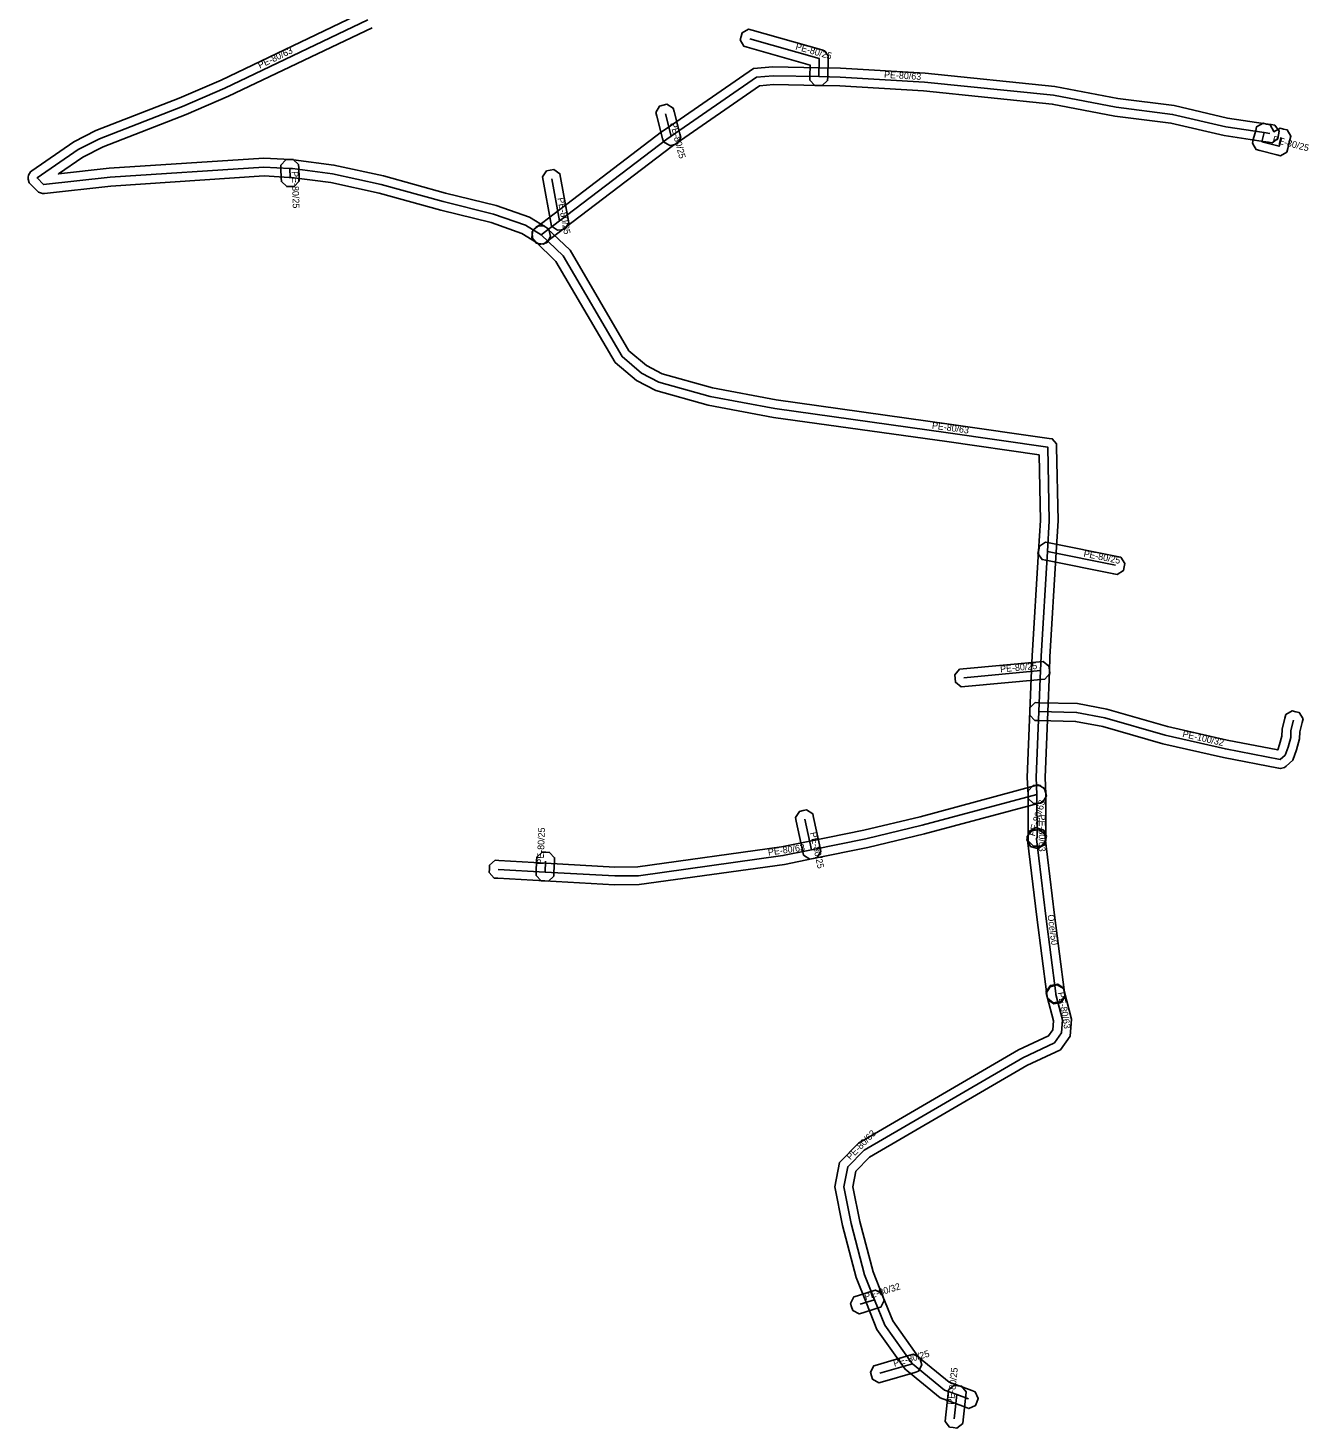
# Model space of a CAD drawing. Extents: x -569373 to -565022, y -1135090 to -1131496.
# Drawn here: x -565683.5 to -565539.4, y -1134292.3 to -1134134.8 of the extents above; entities that cross this region are included whole.
import ezdxf

# ---------------------------------------------------------------- set-up
doc = ezdxf.new("R2010")
doc.units = 0
for name, color, linetype in [('1', 7, 'Continuous'), ('24', 7, 'Continuous'), ('30', 7, 'Continuous')]:
    doc.layers.add(name, color=color, linetype=linetype)

msp = doc.modelspace()

# ---------------------------------------------------------------- linework, layer by layer
at = {"layer": '1'}
msp.add_lwpolyline([(-565644.837, -1134134.732), (-565660.985, -1134142.44), (-565665.759, -1134144.515), (-565675.083, -1134148.145), (-565677.369, -1134149.292), (-565680.107, -1134151.186), (-565674.398, -1134150.554), (-565656.995, -1134149.408), (-565654.019, -1134149.572), (-565653.682, -1134149.594), (-565649.129, -1134150.184), (-565643.55, -1134151.399), (-565636.587, -1134153.333), (-565630.875, -1134154.74), (-565627.127, -1134156.052), (-565625.285, -1134157.189), (-565624.933, -1134157.406), (-565624.742, -1134158.213), (-565624.959, -1134158.565), (-565625.176, -1134158.917), (-565625.983, -1134159.108), (-565626.335, -1134158.891), (-565627.993, -1134157.868), (-565631.445, -1134156.66), (-565637.093, -1134155.267), (-565644.03, -1134153.341), (-565649.471, -1134152.156), (-565653.878, -1134151.586), (-565654.141, -1134151.568), (-565656.985, -1134151.412), (-565674.222, -1134152.546), (-565681.69, -1134153.374), (-565681.92, -1134153.4), (-565682.356, -1134153.243), (-565682.517, -1134153.077), (-565683.237, -1134152.337), (-565683.391, -1134152.179), (-565683.536, -1134151.763), (-565683.515, -1134151.543), (-565683.494, -1134151.324), (-565683.27, -1134150.944), (-565683.089, -1134150.818), (-565678.391, -1134147.568), (-565675.897, -1134146.315), (-565666.521, -1134142.665), (-565661.815, -1134140.62), (-565645.743, -1134132.948)], dxfattribs=at)
for points in [[(-565595.58, -1134140.629), (-565595.57, -1134140.215), (-565595.539, -1134138.951), (-565602.623, -1134136.942), (-565603.021, -1134136.829), (-565603.425, -1134136.105), (-565603.312, -1134135.707), (-565603.199, -1134135.309), (-565602.475, -1134134.905), (-565602.077, -1134135.018), (-565594.247, -1134137.238), (-565593.918, -1134137.331), (-565593.512, -1134137.882), (-565593.52, -1134138.225), (-565593.57, -1134140.265), (-565593.58, -1134140.679), (-565594.181, -1134141.25), (-565594.595, -1134141.24), (-565595.009, -1134141.23)], [(-565626.746, -1134157.496), (-565626.416, -1134157.245), (-565624.356, -1134155.675), (-565612.258, -1134146.461), (-565611.749, -1134146.108), (-565601.928, -1134139.315), (-565599.751, -1134139.139), (-565594.552, -1134139.24), (-565592.132, -1134139.281), (-565582.619, -1134139.853), (-565568.035, -1134141.34), (-565560.953, -1134142.692), (-565554.602, -1134143.494), (-565548.591, -1134144.907), (-565544.313, -1134145.551), (-565543.704, -1134145.641), (-565543.294, -1134145.701), (-565542.801, -1134146.366), (-565542.861, -1134146.776), (-565542.921, -1134147.186), (-565543.586, -1134147.679), (-565543.996, -1134147.619), (-565544.607, -1134147.529), (-565548.969, -1134146.873), (-565554.958, -1134145.466), (-565561.267, -1134144.668), (-565568.325, -1134143.32), (-565582.781, -1134141.847), (-565592.208, -1134141.279), (-565594.588, -1134141.24), (-565599.689, -1134141.141), (-565601.232, -1134141.265), (-565610.611, -1134147.752), (-565611.082, -1134148.079), (-565623.144, -1134157.265), (-565625.204, -1134158.835), (-565625.533, -1134159.086), (-565626.354, -1134158.976), (-565626.605, -1134158.646), (-565626.856, -1134158.317)], [(-565612.044, -1134147.582), (-565612.148, -1134147.181), (-565612.798, -1134144.671), (-565612.902, -1134144.27), (-565612.482, -1134143.556), (-565612.081, -1134143.452), (-565611.68, -1134143.348), (-565610.966, -1134143.768), (-565610.862, -1134144.169), (-565610.212, -1134146.679), (-565610.108, -1134147.08), (-565610.528, -1134147.794), (-565610.929, -1134147.898), (-565611.33, -1134148.002)], [(-565543.388, -1134146.393), (-565543.402, -1134146.447), (-565542.691, -1134146.028), (-565542.29, -1134146.132), (-565541.889, -1134146.235), (-565541.468, -1134146.949), (-565541.572, -1134147.35), (-565541.822, -1134148.32), (-565541.925, -1134148.721), (-565542.639, -1134149.142), (-565543.04, -1134149.038), (-565544.98, -1134148.538), (-565545.382, -1134148.435), (-565545.592, -1134148.076), (-565545.803, -1134147.718), (-565545.697, -1134147.316), (-565545.427, -1134146.286), (-565545.322, -1134145.885), (-565544.607, -1134145.468), (-565544.206, -1134145.573), (-565543.805, -1134145.678)], [(-565653.092, -1134150.127), (-565653.08, -1134150.541), (-565653.05, -1134151.571), (-565653.038, -1134151.985), (-565653.607, -1134152.588), (-565654.021, -1134152.6), (-565654.435, -1134152.612), (-565655.038, -1134152.043), (-565655.05, -1134151.629), (-565655.08, -1134150.599), (-565655.092, -1134150.185), (-565654.523, -1134149.582), (-565654.109, -1134149.57), (-565653.695, -1134149.558)], [(-565624.66, -1134157.057), (-565624.734, -1134156.649), (-565625.594, -1134151.929), (-565625.668, -1134151.521), (-565625.197, -1134150.84), (-565624.789, -1134150.766), (-565624.381, -1134150.692), (-565623.7, -1134151.163), (-565623.626, -1134151.571), (-565622.766, -1134156.291), (-565622.692, -1134156.699), (-565623.163, -1134157.38), (-565623.571, -1134157.454), (-565623.979, -1134157.528)], [(-565625.417, -1134157.031), (-565625.118, -1134157.318), (-565622.557, -1134159.775), (-565615.933, -1134171.078), (-565613.969, -1134172.744), (-565612.192, -1134173.664), (-565606.552, -1134175.235), (-565599.357, -1134176.603), (-565579.9, -1134179.32), (-565568.678, -1134180.93), (-565568.315, -1134180.982), (-565567.828, -1134181.532), (-565567.82, -1134181.899), (-565567.649, -1134190.21), (-565567.862, -1134193.73), (-565568.571, -1134205.492), (-565568.641, -1134207.102), (-565568.831, -1134211.711), (-565569.129, -1134219.067), (-565569.041, -1134220.943), (-565569.022, -1134221.357), (-565569.579, -1134221.97), (-565569.993, -1134221.989), (-565570.407, -1134222.008), (-565571.02, -1134221.451), (-565571.039, -1134221.037), (-565571.131, -1134219.073), (-565570.829, -1134211.629), (-565570.639, -1134207.018), (-565570.569, -1134205.388), (-565569.858, -1134193.61), (-565569.651, -1134190.17), (-565569.802, -1134182.789), (-565580.18, -1134181.3), (-565599.683, -1134178.577), (-565607.008, -1134177.185), (-565612.928, -1134175.536), (-565615.091, -1134174.416), (-565617.487, -1134172.382), (-565624.143, -1134161.025), (-565626.502, -1134158.762), (-565626.801, -1134158.475), (-565626.819, -1134157.647), (-565626.532, -1134157.348), (-565626.245, -1134157.049)], [(-565569.07, -1134192.608), (-565568.664, -1134192.689), (-565561.014, -1134194.219), (-565560.608, -1134194.301), (-565560.148, -1134194.99), (-565560.229, -1134195.396), (-565560.311, -1134195.802), (-565561, -1134196.262), (-565561.406, -1134196.181), (-565569.056, -1134194.651), (-565569.462, -1134194.569), (-565569.922, -1134193.88), (-565569.841, -1134193.474), (-565569.759, -1134193.068)], [(-565578.755, -1134206.903), (-565578.343, -1134206.864), (-565569.733, -1134206.064), (-565569.32, -1134206.026), (-565568.683, -1134206.555), (-565568.644, -1134206.967), (-565568.606, -1134207.38), (-565569.135, -1134208.017), (-565569.547, -1134208.056), (-565578.157, -1134208.856), (-565578.57, -1134208.894), (-565579.207, -1134208.365), (-565579.246, -1134207.953), (-565579.284, -1134207.54)], [(-565540.099, -1134212.493), (-565540.2, -1134212.895), (-565540.465, -1134213.943), (-565540.495, -1134214.73), (-565540.825, -1134215.968), (-565541.248, -1134217.146), (-565542.018, -1134217.808), (-565542.192, -1134217.958), (-565542.635, -1134218.076), (-565542.86, -1134218.032), (-565549.036, -1134216.839), (-565555.859, -1134215.289), (-565562.631, -1134213.344), (-565565.685, -1134212.768), (-565569.854, -1134212.67), (-565570.268, -1134212.66), (-565570.84, -1134212.06), (-565570.83, -1134211.646), (-565570.82, -1134211.232), (-565570.22, -1134210.66), (-565569.806, -1134210.67), (-565565.475, -1134210.772), (-565562.169, -1134211.396), (-565555.361, -1134213.351), (-565548.624, -1134214.881), (-565542.955, -1134215.976), (-565542.952, -1134215.974), (-565542.735, -1134215.372), (-565542.485, -1134214.43), (-565542.455, -1134213.657), (-565542.14, -1134212.405), (-565542.039, -1134212.004), (-565541.327, -1134211.579), (-565540.925, -1134211.68), (-565540.524, -1134211.781)], [(-565569.38, -1134221.848), (-565569.78, -1134221.956), (-565582.694, -1134225.429), (-565589.064, -1134226.947), (-565595.201, -1134228.2), (-565598.452, -1134228.856), (-565614.775, -1134231.129), (-565617.552, -1134231.16), (-565625.426, -1134230.718), (-565630.687, -1134230.418), (-565631.1, -1134230.394), (-565631.652, -1134229.776), (-565631.628, -1134229.363), (-565631.604, -1134228.95), (-565630.986, -1134228.398), (-565630.573, -1134228.422), (-565625.314, -1134228.722), (-565617.508, -1134229.16), (-565614.925, -1134229.131), (-565598.788, -1134226.884), (-565595.599, -1134226.24), (-565589.496, -1134224.993), (-565583.186, -1134223.491), (-565570.3, -1134220.024), (-565569.9, -1134219.917), (-565569.182, -1134220.33), (-565569.074, -1134220.73), (-565568.967, -1134221.13)], [(-565569.041, -1134220.574), (-565569.04, -1134220.988), (-565569.03, -1134225.798), (-565569.029, -1134226.212), (-565569.614, -1134226.799), (-565570.028, -1134226.8), (-565570.442, -1134226.801), (-565571.029, -1134226.216), (-565571.03, -1134225.802), (-565571.04, -1134220.992), (-565571.041, -1134220.578), (-565570.456, -1134219.991), (-565570.042, -1134219.99), (-565569.628, -1134219.989)], [(-565596.291, -1134227.835), (-565596.378, -1134227.43), (-565597.118, -1134223.99), (-565597.205, -1134223.585), (-565596.755, -1134222.889), (-565596.35, -1134222.802), (-565595.945, -1134222.715), (-565595.249, -1134223.165), (-565595.162, -1134223.57), (-565594.422, -1134227.01), (-565594.335, -1134227.415), (-565594.785, -1134228.111), (-565595.19, -1134228.198), (-565595.595, -1134228.285)], [(-565568.953, -1134225.691), (-565569.072, -1134226.087), (-565569.132, -1134226.287), (-565569.251, -1134226.684), (-565569.981, -1134227.077), (-565570.377, -1134226.958), (-565570.774, -1134226.839), (-565571.167, -1134226.109), (-565571.048, -1134225.713), (-565570.988, -1134225.513), (-565570.869, -1134225.116), (-565570.139, -1134224.723), (-565569.743, -1134224.842), (-565569.346, -1134224.961)], [(-565569.146, -1134225.47), (-565569.097, -1134225.881), (-565568.058, -1134234.557), (-565566.938, -1134243.252), (-565566.885, -1134243.663), (-565567.392, -1134244.319), (-565567.802, -1134244.372), (-565568.213, -1134244.425), (-565568.869, -1134243.918), (-565568.922, -1134243.508), (-565570.042, -1134234.803), (-565571.083, -1134226.119), (-565571.132, -1134225.708), (-565570.62, -1134225.056), (-565570.209, -1134225.007), (-565569.798, -1134224.958)], [(-565626.386, -1134230.093), (-565626.369, -1134229.679), (-565626.319, -1134228.449), (-565626.302, -1134228.035), (-565625.693, -1134227.474), (-565625.279, -1134227.491), (-565624.865, -1134227.508), (-565624.304, -1134228.117), (-565624.321, -1134228.531), (-565624.371, -1134229.761), (-565624.388, -1134230.175), (-565624.997, -1134230.736), (-565625.411, -1134230.719), (-565625.825, -1134230.702)], [(-565586.266, -1134280.219), (-565583.379, -1134284.297), (-565579.918, -1134287.109), (-565578.692, -1134287.563), (-565577.38, -1134288.053), (-565576.992, -1134288.198), (-565576.648, -1134288.952), (-565576.793, -1134289.34), (-565576.938, -1134289.728), (-565577.692, -1134290.072), (-565578.08, -1134289.927), (-565579.388, -1134289.437), (-565580.922, -1134288.871), (-565584.691, -1134285.808), (-565584.865, -1134285.659), (-565588.034, -1134281.181), (-565589.229, -1134278.201), (-565590.372, -1134275.332), (-565591.895, -1134269.474), (-565592.769, -1134265.127), (-565592.257, -1134262.396), (-565590.109, -1134260.213), (-565572.097, -1134249.725), (-565568.737, -1134248.13), (-565568.262, -1134247.454), (-565568.172, -1134246.444), (-565568.878, -1134243.743), (-565568.982, -1134243.342), (-565568.564, -1134242.627), (-565568.163, -1134242.522), (-565567.762, -1134242.418), (-565567.047, -1134242.836), (-565566.942, -1134243.237), (-565566.148, -1134246.276), (-565566.318, -1134248.166), (-565567.403, -1134249.71), (-565571.163, -1134251.495), (-565588.871, -1134261.807), (-565590.403, -1134263.364), (-565590.731, -1134265.113), (-565589.945, -1134269.026), (-565588.468, -1134274.708), (-565587.371, -1134277.459)], [(-565567.02, -1134242.793), (-565566.946, -1134243.201), (-565566.926, -1134243.311), (-565566.852, -1134243.719), (-565567.323, -1134244.4), (-565567.731, -1134244.474), (-565568.139, -1134244.548), (-565568.82, -1134244.077), (-565568.894, -1134243.669), (-565568.914, -1134243.559), (-565568.988, -1134243.151), (-565568.517, -1134242.47), (-565568.109, -1134242.396), (-565567.701, -1134242.322)], [(-565587.606, -1134278.661), (-565588.001, -1134278.784), (-565589.631, -1134279.294), (-565590.027, -1134279.418), (-565590.761, -1134279.034), (-565590.884, -1134278.639), (-565591.008, -1134278.243), (-565590.624, -1134277.509), (-565590.229, -1134277.386), (-565588.599, -1134276.876), (-565588.203, -1134276.752), (-565587.469, -1134277.136), (-565587.346, -1134277.531), (-565587.222, -1134277.927)], [(-565583.373, -1134285.884), (-565583.771, -1134286), (-565587.421, -1134287.06), (-565587.819, -1134287.176), (-565588.544, -1134286.777), (-565588.66, -1134286.379), (-565588.776, -1134285.981), (-565588.377, -1134285.256), (-565587.979, -1134285.14), (-565584.329, -1134284.08), (-565583.931, -1134283.964), (-565583.206, -1134284.363), (-565583.09, -1134284.761), (-565582.974, -1134285.159)], [(-565578, -1134288.198), (-565578.046, -1134288.61), (-565578.346, -1134291.33), (-565578.392, -1134291.742), (-565579.038, -1134292.26), (-565579.45, -1134292.214), (-565579.862, -1134292.168), (-565580.38, -1134291.522), (-565580.334, -1134291.11), (-565580.034, -1134288.39), (-565579.988, -1134287.978), (-565579.342, -1134287.46), (-565578.93, -1134287.506), (-565578.518, -1134287.552)]]:
    msp.add_lwpolyline(points, close=True, dxfattribs=at)
at = {"layer": '24'}
for points in [[(-565645.29, -1134133.84), (-565661.4, -1134141.53), (-565666.14, -1134143.59), (-565675.49, -1134147.23), (-565677.88, -1134148.43), (-565682.52, -1134151.64), (-565681.8, -1134152.38), (-565674.31, -1134151.55), (-565656.99, -1134150.41), (-565654.08, -1134150.57), (-565653.78, -1134150.59), (-565649.3, -1134151.17), (-565643.79, -1134152.37), (-565636.84, -1134154.3), (-565631.16, -1134155.7), (-565627.56, -1134156.96), (-565625.81, -1134158.04)], [(-565594.57, -1134140.24), (-565594.52, -1134138.2), (-565602.35, -1134135.98)], [(-565625.81, -1134158.04), (-565623.75, -1134156.47), (-565611.67, -1134147.27), (-565611.18, -1134146.93), (-565601.58, -1134140.29), (-565599.72, -1134140.14), (-565594.57, -1134140.24), (-565592.17, -1134140.28), (-565582.7, -1134140.85), (-565568.18, -1134142.33), (-565561.11, -1134143.68), (-565554.78, -1134144.48), (-565548.78, -1134145.89), (-565544.46, -1134146.54), (-565543.85, -1134146.63)], [(-565611.18, -1134146.93), (-565611.83, -1134144.42)], [(-565544.46, -1134146.54), (-565544.73, -1134147.57), (-565542.79, -1134148.07), (-565542.54, -1134147.1)], [(-565654.08, -1134150.57), (-565654.05, -1134151.6)], [(-565623.75, -1134156.47), (-565624.61, -1134151.75)], [(-565625.81, -1134158.04), (-565623.35, -1134160.4), (-565616.71, -1134171.73), (-565614.53, -1134173.58), (-565612.56, -1134174.6), (-565606.78, -1134176.21), (-565599.52, -1134177.59), (-565580.04, -1134180.31), (-565568.82, -1134181.92), (-565568.65, -1134190.19), (-565568.86, -1134193.67), (-565569.57, -1134205.44), (-565569.64, -1134207.06), (-565569.83, -1134211.67), (-565570.13, -1134219.07), (-565570.04, -1134220.99)], [(-565568.86, -1134193.67), (-565561.21, -1134195.2)], [(-565578.25, -1134207.86), (-565569.64, -1134207.06)], [(-565541.17, -1134212.65), (-565541.46, -1134213.8), (-565541.49, -1134214.58), (-565541.78, -1134215.67), (-565542.1, -1134216.56), (-565542.67, -1134217.05), (-565548.83, -1134215.86), (-565555.61, -1134214.32), (-565562.4, -1134212.37), (-565565.58, -1134211.77), (-565569.83, -1134211.67)], [(-565570.04, -1134220.99), (-565582.94, -1134224.46), (-565589.28, -1134225.97), (-565595.4, -1134227.22), (-565598.62, -1134227.87), (-565614.85, -1134230.13), (-565617.53, -1134230.16), (-565625.37, -1134229.72), (-565630.63, -1134229.42)], [(-565570.04, -1134220.99), (-565570.03, -1134225.8)], [(-565595.4, -1134227.22), (-565596.14, -1134223.78)], [(-565570.03, -1134225.8), (-565570.09, -1134226)], [(-565570.09, -1134226), (-565569.05, -1134234.68), (-565567.93, -1134243.38)], [(-565625.37, -1134229.72), (-565625.32, -1134228.49)], [(-565567.91, -1134243.49), (-565567.16, -1134246.36), (-565567.29, -1134247.81), (-565568.07, -1134248.92), (-565571.63, -1134250.61), (-565589.49, -1134261.01), (-565591.33, -1134262.88), (-565591.75, -1134265.12), (-565590.92, -1134269.25), (-565589.42, -1134275.02), (-565588.3, -1134277.83), (-565587.15, -1134280.7), (-565584.12, -1134284.98), (-565584.05, -1134285.04), (-565580.42, -1134287.99), (-565579.04, -1134288.5), (-565577.73, -1134288.99)], [(-565567.93, -1134243.38), (-565567.91, -1134243.49)], [(-565588.3, -1134277.83), (-565589.93, -1134278.34)], [(-565584.05, -1134285.04), (-565587.7, -1134286.1)], [(-565579.04, -1134288.5), (-565579.34, -1134291.22)]]:
    msp.add_lwpolyline(points, dxfattribs=at)

# ---------------------------------------------------------------- texts
at = {"layer": '30'}
for s, rotation, p in [('PE-80/25', 344.17065, (-565597.253, -1134137.168)), ('PE-80/63', 25.51716, (-565657.454, -1134139.351)), ('PE-80/63', 356.55552, (-565587.254, -1134140.364)), ('PE-80/25', 284.51861, (-565611.305, -1134145.475)), ('PE-80/25', 345.54757, (-565543.591, -1134147.612)), ('PE-80/25', 271.66834, (-565653.865, -1134150.885)), ('PE-80/25', 280.32621, (-565623.98, -1134153.91)), ('PE-80/63', 352.05116, (-565581.885, -1134179.824)), ('PE-80/25', 348.69007, (-565564.835, -1134194.235)), ('PE-80/25', 5.30841, (-565574.145, -1134207.26)), ('PE-100/32', 347.20304, (-565553.72, -1134214.504)), ('PE-80/63', 73.30076, (-565570.274, -1134225.748)), ('PE-80/25', 87.67218, (-565625.545, -1134228.905)), ('PE-80/63', 270.11912, (-565569.835, -1134223.245)), ('PE-80/25', 282.14025, (-565595.57, -1134225.3)), ('PE-80/63', 7.92737, (-565600.246, -1134227.869)), ('Ocel/50', 277.33566, (-565568.842, -1134234.544)), ('PE-80/63', 280.30485, (-565567.711, -1134243.284)), ('PE-80/63', 45.4633, (-565591.019, -1134262.161)), ('PE-80/32', 17.37404, (-565589.315, -1134277.885)), ('PE-80/25', 16.19388, (-565586.075, -1134285.37)), ('PE-80/25', 83.70605, (-565579.39, -1134289.66))]:
    msp.add_text(s, height=0.75, rotation=rotation, dxfattribs=at).set_placement(p)

doc.saveas('drawing.dxf')
